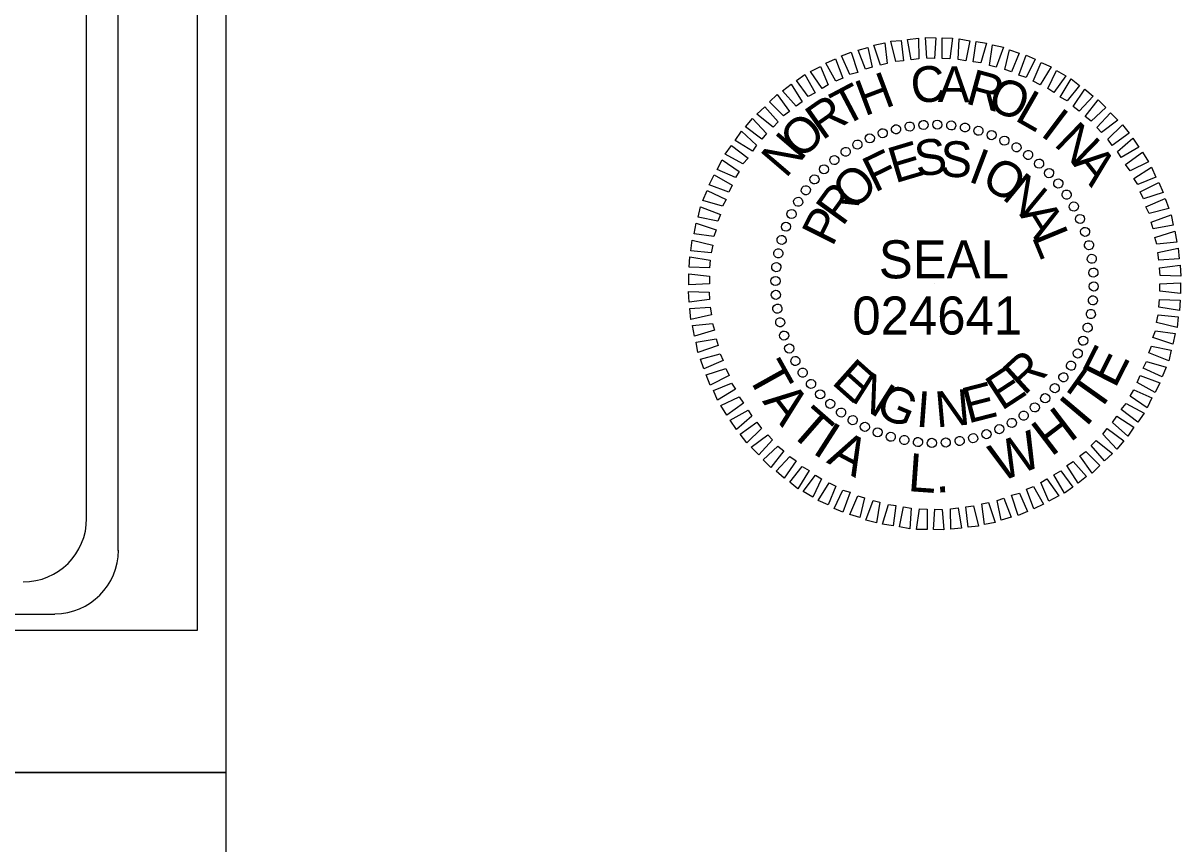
# Model space of a CAD drawing. Extents: x 2241278 to 2254132, y 649924 to 670434.
# Drawn here: x 2252819 to 2253731, y 660843 to 661490 of the extents above; entities that cross this region are included whole.
import ezdxf

# ---------------------------------------------------------------- set-up
doc = ezdxf.new("R2010")
doc.units = 0
for name, color, linetype in [('Sheet Cutting Line CELL', 7, 'Continuous'), ('Sheet Plot Border Inside CELL', 7, 'Continuous'), ('Sheet Plot Border Outside CELL', 7, 'Continuous'), ('Sheet Professional Seal CELL', 7, 'Continuous'), ('Sheet Title CELL', 7, 'Continuous')]:
    doc.layers.add(name, color=color, linetype=linetype)

msp = doc.modelspace()

# ---------------------------------------------------------------- linework, layer by layer
at = {"layer": 'Sheet Cutting Line CELL'}
for p, q in [((2244558.77, 660899.17), (2252978.77, 660899.17)), ((2252978.77, 660899.17), (2244558.77, 660899.17))]:
    msp.add_line(p, q, dxfattribs=at)
at = {"layer": 'Sheet Plot Border Inside CELL'}
msp.add_lwpolyline([(2244623.77, 661011.36), (2252956.27, 661011.36), (2252956.27, 666286.86), (2244623.77, 666286.86)], close=True, dxfattribs=at)
at = {"layer": 'Sheet Plot Border Outside CELL'}
for points in [[(2252978.77, 666399.11), (2244558.77, 666399.11), (2244558.77, 660899.17), (2252978.77, 660899.17)], [(2244558.77, 655399.17), (2252978.77, 655399.17), (2252978.77, 660899.17), (2244558.77, 660899.17)]]:
    msp.add_lwpolyline(points, close=True, dxfattribs=at)
at = {"layer": 'Sheet Professional Seal CELL'}
for p, q in [((2253517.4, 661408.09), (2253517.4, 661408.09)), ((2253528.15, 661409.6), (2253528.15, 661409.6)), ((2253539.15, 661409.85), (2253539.15, 661409.85)), ((2253550.15, 661409.1), (2253550.15, 661409.1)), ((2253485.9, 661399.08), (2253485.9, 661399.08)), ((2253495.9, 661403.09), (2253495.9, 661403.09)), ((2253506.4, 661406.09), (2253506.4, 661406.09)), ((2253560.9, 661407.35), (2253560.9, 661407.35)), ((2253571.4, 661405.11), (2253571.4, 661405.11)), ((2253581.9, 661401.61), (2253581.9, 661401.61)), ((2253476.15, 661394.08), (2253476.15, 661394.08)), ((2253591.9, 661397.11), (2253591.9, 661397.11)), ((2253601.65, 661392.11), (2253601.65, 661392.11)), ((2253457.91, 661382.08), (2253457.91, 661382.08)), ((2253466.65, 661388.33), (2253466.65, 661388.33)), ((2253610.66, 661385.87), (2253610.66, 661385.87)), ((2253449.66, 661374.58), (2253449.66, 661374.58)), ((2253619.41, 661379.12), (2253619.41, 661379.12)), ((2253627.16, 661371.62), (2253627.16, 661371.62)), ((2253442.16, 661366.82), (2253442.16, 661366.82)), ((2253634.66, 661363.37), (2253634.66, 661363.37)), ((2253435.41, 661358.07), (2253435.41, 661358.07)), ((2253640.91, 661354.62), (2253640.91, 661354.62)), ((2253429.16, 661349.07), (2253429.16, 661349.07)), ((2253646.67, 661345.12), (2253646.67, 661345.12)), ((2253424.17, 661339.32), (2253424.17, 661339.32)), ((2253651.67, 661335.38), (2253651.67, 661335.38)), ((2253419.67, 661329.32), (2253419.67, 661329.32)), ((2253416.17, 661318.82), (2253416.17, 661318.82)), ((2253655.67, 661325.38), (2253655.67, 661325.38)), ((2253413.92, 661308.32), (2253413.92, 661308.32)), ((2253658.67, 661314.88), (2253658.67, 661314.88)), ((2253660.68, 661303.88), (2253660.68, 661303.88)), ((2253412.18, 661297.57), (2253412.18, 661297.57)), ((2253662.18, 661293.13), (2253662.18, 661293.13)), ((2253411.43, 661286.57), (2253411.43, 661286.57)), ((2253536.93, 661284.35), (2253536.93, 661284.35)), ((2253662.43, 661282.13), (2253662.43, 661282.13)), ((2253411.68, 661275.57), (2253411.68, 661275.57)), ((2253661.68, 661271.13), (2253661.68, 661271.13)), ((2253413.19, 661264.82), (2253413.19, 661264.82)), ((2253415.19, 661253.82), (2253415.19, 661253.82)), ((2253659.94, 661260.38), (2253659.94, 661260.38)), ((2253657.69, 661249.88), (2253657.69, 661249.88)), ((2253418.19, 661243.32), (2253418.19, 661243.32)), ((2253654.19, 661239.38), (2253654.19, 661239.38)), ((2253422.19, 661233.32), (2253422.19, 661233.32)), ((2253649.69, 661229.38), (2253649.69, 661229.38)), ((2253427.2, 661223.57), (2253427.2, 661223.57)), ((2253644.7, 661219.62), (2253644.7, 661219.62)), ((2253432.95, 661214.07), (2253432.95, 661214.07)), ((2253638.45, 661210.62), (2253638.45, 661210.62)), ((2253439.2, 661205.32), (2253439.2, 661205.32)), ((2253631.7, 661201.87), (2253631.7, 661201.87)), ((2253446.7, 661197.07), (2253446.7, 661197.07)), ((2253454.45, 661189.58), (2253454.45, 661189.58)), ((2253624.2, 661194.12), (2253624.2, 661194.12)), ((2253463.21, 661182.83), (2253463.21, 661182.83)), ((2253607.21, 661180.36), (2253607.21, 661180.36)), ((2253615.96, 661186.62), (2253615.96, 661186.62)), ((2253472.21, 661176.58), (2253472.21, 661176.58)), ((2253481.96, 661171.58), (2253481.96, 661171.58)), ((2253597.71, 661174.61), (2253597.71, 661174.61)), ((2253491.96, 661167.09), (2253491.96, 661167.09)), ((2253502.46, 661163.59), (2253502.46, 661163.59)), ((2253512.96, 661161.34), (2253512.96, 661161.34)), ((2253567.46, 661162.6), (2253567.46, 661162.6)), ((2253577.96, 661165.61), (2253577.96, 661165.61)), ((2253587.96, 661169.61), (2253587.96, 661169.61)), ((2253523.71, 661159.59), (2253523.71, 661159.59)), ((2253534.71, 661158.85), (2253534.71, 661158.85)), ((2253545.71, 661159.1), (2253545.71, 661159.1)), ((2253556.46, 661160.6), (2253556.46, 661160.6))]:
    msp.add_line(p, q, dxfattribs=at)
for points in [[(2253494.39, 661456.59), (2253489.13, 661472.34), (2253497.63, 661474.09), (2253499.64, 661457.84)], [(2253506.39, 661459.34), (2253502.38, 661475.34), (2253510.63, 661476.09), (2253512.39, 661460.09)], [(2253518.39, 661460.84), (2253515.63, 661476.84), (2253524.13, 661477.84), (2253524.39, 661461.59)], [(2253530.89, 661462.1), (2253529.63, 661478.35), (2253537.88, 661478.1), (2253536.89, 661461.85)], [(2253542.89, 661461.85), (2253542.88, 661478.1), (2253551.13, 661477.85), (2253548.89, 661461.6)], [(2253555.39, 661461.1), (2253556.38, 661477.35), (2253564.63, 661475.85), (2253561.39, 661460.1)], [(2253567.39, 661459.1), (2253569.63, 661475.11), (2253577.88, 661473.86), (2253573.39, 661458.36)], [(2253580.14, 661456.36), (2253582.63, 661472.61), (2253591.13, 661470.61), (2253585.39, 661455.11)], [(2253470.14, 661449.33), (2253463.64, 661463.83), (2253471.14, 661466.83), (2253476.39, 661450.83)], [(2253482.39, 661453.33), (2253476.63, 661468.33), (2253484.38, 661470.58), (2253487.64, 661455.08)], [(2253592.14, 661453.11), (2253595.88, 661468.61), (2253603.64, 661466.11), (2253597.39, 661451.36)], [(2253603.39, 661448.61), (2253609.14, 661464.37), (2253616.14, 661461.37), (2253609.14, 661446.87)], [(2253448.39, 661438.08), (2253439.14, 661451.57), (2253446.89, 661455.57), (2253453.14, 661441.08)], [(2253459.14, 661444.08), (2253451.14, 661458.08), (2253458.89, 661461.58), (2253464.64, 661446.33)], [(2253614.64, 661443.87), (2253620.89, 661458.62), (2253628.64, 661455.12), (2253620.14, 661441.12)], [(2253437.39, 661431.82), (2253428.14, 661444.57), (2253434.64, 661449.32), (2253442.89, 661434.82)], [(2253626.14, 661438.12), (2253632.89, 661452.37), (2253640.39, 661448.12), (2253630.89, 661435.12)], [(2253635.89, 661431.37), (2253644.64, 661445.87), (2253651.14, 661440.63), (2253641.39, 661428.37)], [(2253427.9, 661424.32), (2253417.14, 661436.32), (2253423.89, 661441.57), (2253432.64, 661427.57)], [(2253646.15, 661423.87), (2253655.39, 661437.63), (2253661.89, 661432.13), (2253650.9, 661420.38)], [(2253417.9, 661416.57), (2253406.89, 661427.56), (2253412.89, 661433.57), (2253422.65, 661420.07)], [(2253655.65, 661416.13), (2253665.89, 661429.13), (2253671.9, 661423.13), (2253660.4, 661412.38)], [(2253409.65, 661407.82), (2253396.9, 661418.06), (2253403.15, 661423.81), (2253413.65, 661411.82)], [(2253664.65, 661407.38), (2253675.4, 661419.13), (2253681.4, 661413.13), (2253668.4, 661403.38)], [(2253400.9, 661398.31), (2253387.9, 661408.06), (2253393.4, 661414.56), (2253404.4, 661402.81)], [(2253673.4, 661398.38), (2253684.9, 661409.63), (2253690.15, 661402.89), (2253676.9, 661393.38)], [(2253393.4, 661388.81), (2253379.9, 661397.31), (2253384.65, 661404.56), (2253396.65, 661393.56)], [(2253680.9, 661388.63), (2253693.15, 661399.14), (2253697.9, 661391.89), (2253683.91, 661383.88)], [(2253385.91, 661378.81), (2253371.91, 661386.31), (2253376.9, 661393.31), (2253389.91, 661383.31)], [(2253379.91, 661368.06), (2253365.66, 661374.3), (2253369.41, 661382.06), (2253382.91, 661372.81)], [(2253687.41, 661378.38), (2253700.65, 661387.89), (2253705.41, 661380.39), (2253690.91, 661373.39)], [(2253693.91, 661367.39), (2253707.91, 661376.14), (2253711.16, 661368.39), (2253696.91, 661362.64)], [(2253374.91, 661356.56), (2253359.41, 661362.3), (2253363.16, 661370.05), (2253377.41, 661362.06)], [(2253698.91, 661356.64), (2253713.66, 661364.14), (2253716.91, 661356.14), (2253701.41, 661351.14)], [(2253369.92, 661345.56), (2253354.41, 661350.05), (2253357.66, 661357.8), (2253372.66, 661350.81)], [(2253366.17, 661333.55), (2253350.67, 661336.8), (2253352.42, 661345.05), (2253368.17, 661338.81)], [(2253703.42, 661344.89), (2253718.66, 661351.39), (2253721.42, 661343.64), (2253705.92, 661339.64)], [(2253707.42, 661332.89), (2253723.42, 661338.64), (2253724.92, 661330.39), (2253709.17, 661327.64)], [(2253362.92, 661321.55), (2253347.42, 661323.55), (2253349.17, 661332.05), (2253364.92, 661326.8)], [(2253710.42, 661320.89), (2253726.17, 661325.64), (2253727.67, 661317.14), (2253711.92, 661315.64)], [(2253360.92, 661308.8), (2253344.92, 661310.3), (2253345.92, 661318.8), (2253362.17, 661314.8)], [(2253712.67, 661308.89), (2253728.92, 661312.4), (2253729.68, 661303.9), (2253713.68, 661302.89)], [(2253359.68, 661296.8), (2253343.43, 661297.3), (2253343.93, 661305.55), (2253360.18, 661302.8)], [(2253714.18, 661296.89), (2253730.43, 661298.9), (2253730.93, 661290.4), (2253714.68, 661290.89)], [(2253359.43, 661284.3), (2253343.18, 661283.55), (2253343.18, 661292.05), (2253359.43, 661290.3)], [(2253714.43, 661284.39), (2253730.68, 661285.15), (2253730.68, 661276.65), (2253714.43, 661278.39)], [(2253359.68, 661271.8), (2253343.43, 661269.8), (2253342.93, 661278.3), (2253359.18, 661277.8)], [(2253714.18, 661271.89), (2253730.43, 661271.4), (2253729.94, 661263.15), (2253713.69, 661265.89)], [(2253361.19, 661259.8), (2253344.94, 661256.3), (2253344.19, 661264.8), (2253360.19, 661265.8)], [(2253363.44, 661247.8), (2253347.69, 661243.05), (2253346.19, 661251.55), (2253361.94, 661253.05)], [(2253712.94, 661259.89), (2253728.94, 661258.4), (2253727.94, 661249.89), (2253711.69, 661253.89)], [(2253710.94, 661247.14), (2253726.44, 661245.14), (2253724.69, 661236.64), (2253708.94, 661241.89)], [(2253366.44, 661235.8), (2253350.44, 661230.05), (2253348.94, 661238.3), (2253364.69, 661241.05)], [(2253707.69, 661235.14), (2253723.19, 661231.89), (2253721.45, 661223.64), (2253705.69, 661229.89)], [(2253370.45, 661223.81), (2253355.2, 661217.3), (2253352.45, 661225.05), (2253367.94, 661229.05)], [(2253374.95, 661212.06), (2253360.2, 661204.55), (2253356.95, 661212.55), (2253372.45, 661217.56)], [(2253703.95, 661223.14), (2253719.45, 661218.64), (2253716.2, 661210.89), (2253701.2, 661217.89)], [(2253698.95, 661212.14), (2253714.45, 661206.39), (2253710.7, 661198.64), (2253696.45, 661206.64)], [(2253379.95, 661201.31), (2253365.95, 661192.55), (2253362.7, 661200.3), (2253376.95, 661206.06)], [(2253693.95, 661200.64), (2253708.2, 661194.39), (2253704.46, 661186.64), (2253690.95, 661195.89)], [(2253386.45, 661190.31), (2253373.21, 661180.81), (2253368.45, 661188.31), (2253382.95, 661195.31)], [(2253687.95, 661189.88), (2253701.96, 661182.39), (2253696.96, 661175.39), (2253683.96, 661185.38)], [(2253392.96, 661180.06), (2253380.71, 661169.56), (2253375.96, 661176.81), (2253389.96, 661184.81)], [(2253680.46, 661179.88), (2253693.96, 661171.39), (2253689.21, 661164.14), (2253677.21, 661175.13)], [(2253400.46, 661170.31), (2253388.96, 661159.06), (2253383.71, 661165.81), (2253396.96, 661175.31)], [(2253409.21, 661161.32), (2253398.46, 661149.56), (2253392.46, 661155.56), (2253405.46, 661165.31)], [(2253672.96, 661170.38), (2253685.96, 661160.63), (2253680.46, 661154.13), (2253669.46, 661165.88)], [(2253418.21, 661152.57), (2253407.97, 661139.56), (2253401.97, 661145.56), (2253413.46, 661156.32)], [(2253664.21, 661160.88), (2253676.96, 661150.63), (2253670.72, 661144.88), (2253660.21, 661156.88)], [(2253427.72, 661144.82), (2253418.47, 661131.07), (2253411.97, 661136.57), (2253422.96, 661148.32)], [(2253645.97, 661144.37), (2253656.72, 661132.38), (2253649.97, 661127.13), (2253641.22, 661141.12)], [(2253655.96, 661152.13), (2253666.97, 661141.13), (2253660.97, 661135.13), (2253651.21, 661148.63)], [(2253437.97, 661137.32), (2253429.22, 661122.82), (2253422.72, 661128.07), (2253432.47, 661140.32)], [(2253636.47, 661136.87), (2253645.72, 661124.12), (2253639.22, 661119.37), (2253630.97, 661133.87)], [(2253447.72, 661130.57), (2253440.97, 661116.32), (2253433.47, 661120.57), (2253442.97, 661133.57)], [(2253459.22, 661124.83), (2253452.97, 661110.08), (2253445.22, 661113.57), (2253453.72, 661127.58)], [(2253625.47, 661130.62), (2253634.72, 661117.12), (2253626.97, 661113.12), (2253620.72, 661127.62)], [(2253470.47, 661120.08), (2253464.73, 661104.33), (2253457.72, 661107.33), (2253464.72, 661121.83)], [(2253481.72, 661115.58), (2253477.98, 661100.08), (2253470.23, 661102.58), (2253476.47, 661117.33)], [(2253603.72, 661119.36), (2253610.23, 661104.87), (2253602.73, 661101.86), (2253597.47, 661117.86)], [(2253614.72, 661124.62), (2253622.72, 661110.62), (2253614.98, 661107.12), (2253609.22, 661122.37)], [(2253493.72, 661112.34), (2253491.23, 661096.09), (2253482.73, 661098.08), (2253488.47, 661113.59)], [(2253506.47, 661109.59), (2253504.23, 661093.59), (2253495.98, 661094.84), (2253500.47, 661110.34)], [(2253518.47, 661107.59), (2253517.48, 661091.34), (2253509.23, 661092.84), (2253512.47, 661108.59)], [(2253530.98, 661106.85), (2253530.98, 661090.6), (2253522.73, 661090.84), (2253524.98, 661107.09)], [(2253542.98, 661106.6), (2253544.23, 661090.35), (2253535.98, 661090.6), (2253536.98, 661106.85)], [(2253555.47, 661107.85), (2253558.23, 661091.85), (2253549.73, 661090.85), (2253549.48, 661107.1)], [(2253567.47, 661109.35), (2253571.48, 661093.36), (2253563.23, 661092.6), (2253561.47, 661108.6)], [(2253579.47, 661112.11), (2253584.73, 661096.36), (2253576.23, 661094.61), (2253574.22, 661110.86)], [(2253591.47, 661115.36), (2253597.23, 661100.36), (2253589.48, 661098.11), (2253586.22, 661113.61)]]:
    msp.add_lwpolyline(points, close=True, dxfattribs=at)
for centre, major_axis in [((2253506.56, 661406.01), (-0.87, 3.49)), ((2253517.28, 661408.2), (-0.56, 3.56)), ((2253528.15, 661409.44), (-0.25, 3.59)), ((2253539.09, 661409.73), (0.06, 3.6)), ((2253550.01, 661409.06), (0.38, 3.58)), ((2253560.83, 661407.45), (0.69, 3.53)), ((2253571.47, 661404.9), (0.99, 3.46)), ((2253485.9, 661398.89), (-1.47, 3.29)), ((2253496.07, 661402.91), (-1.17, 3.4)), ((2253581.84, 661401.43), (1.29, 3.36)), ((2253591.87, 661397.07), (1.58, 3.24)), ((2253466.78, 661388.29), (-2.01, 2.98)), ((2253476.11, 661394.01), (-1.75, 3.15)), ((2253601.49, 661391.85), (1.85, 3.09)), ((2253610.61, 661385.82), (2.12, 2.91)), ((2253457.99, 661381.78), (-2.27, 2.8)), ((2253619.18, 661379.01), (2.36, 2.72)), ((2253449.8, 661374.53), (-2.5, 2.59)), ((2253627.11, 661371.48), (2.59, 2.5)), ((2253435.46, 661358.03), (-2.91, 2.12)), ((2253442.27, 661366.59), (-2.72, 2.36)), ((2253634.37, 661363.29), (2.8, 2.27)), ((2253429.43, 661348.91), (-3.09, 1.85)), ((2253640.87, 661354.5), (2.98, 2.01)), ((2253646.59, 661345.17), (3.15, 1.75)), ((2253424.21, 661339.29), (-3.24, 1.58)), ((2253651.48, 661335.38), (3.29, 1.47)), ((2253419.85, 661329.26), (-3.36, 1.29)), ((2253655.49, 661325.2), (3.4, 1.17)), ((2253416.38, 661318.88), (-3.46, 0.99)), ((2253658.6, 661314.71), (3.49, 0.87)), ((2253413.83, 661308.24), (-3.53, 0.69)), ((2253660.78, 661304), (3.56, 0.56)), ((2253412.21, 661297.42), (-3.58, 0.38)), ((2253411.55, 661286.5), (-3.6, 0.06)), ((2253662.02, 661293.13), (3.59, 0.25)), ((2253662.31, 661282.19), (3.6, -0.06)), ((2253411.84, 661275.57), (-3.59, -0.25)), ((2253661.65, 661271.27), (3.58, -0.38)), ((2253413.08, 661264.7), (-3.56, -0.56)), ((2253660.03, 661260.45), (3.53, -0.69)), ((2253415.26, 661253.98), (-3.49, -0.87)), ((2253657.48, 661249.81), (3.46, -0.99)), ((2253418.37, 661243.49), (-3.4, -1.17)), ((2253654.01, 661239.44), (3.36, -1.29)), ((2253422.38, 661233.31), (-3.29, -1.47)), ((2253427.27, 661223.52), (-3.15, -1.75)), ((2253649.65, 661229.4), (3.24, -1.58)), ((2253432.99, 661214.2), (-2.98, -2.01)), ((2253644.44, 661219.79), (3.09, -1.85)), ((2253439.5, 661205.41), (-2.8, -2.27)), ((2253638.4, 661210.66), (2.91, -2.12)), ((2253446.75, 661197.21), (-2.59, -2.5)), ((2253624.06, 661194.16), (2.5, -2.59)), ((2253631.59, 661202.1), (2.72, -2.36)), ((2253454.68, 661189.69), (-2.36, -2.72)), ((2253615.87, 661186.91), (2.27, -2.8)), ((2253463.25, 661182.88), (-2.12, -2.91)), ((2253472.37, 661176.84), (-1.85, -3.09)), ((2253607.08, 661180.4), (2.01, -2.98)), ((2253481.99, 661171.62), (-1.58, -3.24)), ((2253492.02, 661167.26), (-1.29, -3.36)), ((2253587.96, 661169.8), (1.47, -3.29)), ((2253597.75, 661174.69), (1.75, -3.15)), ((2253502.4, 661163.8), (-0.99, -3.46)), ((2253513.03, 661161.25), (-0.69, -3.53)), ((2253523.85, 661159.63), (-0.38, -3.58)), ((2253534.77, 661158.97), (-0.06, -3.6)), ((2253545.71, 661159.25), (0.25, -3.59)), ((2253556.58, 661160.5), (0.56, -3.56)), ((2253567.3, 661162.68), (0.87, -3.49)), ((2253577.79, 661165.79), (1.17, -3.4))]:
    msp.add_ellipse(centre, major_axis=major_axis, ratio=0.999708, dxfattribs=at)
at = {"layer": 'Sheet Title CELL'}
for points in [[(2252893.77, 661074.17), (2252893.77, 666224.11)], [(2252868.77, 661099.17), (2252868.77, 661899.17)], [(2245443.77, 661024.11), (2252843.77, 661024.11)]]:
    msp.add_lwpolyline(points, dxfattribs=at)
for centre in [(2252818.79, 661099.4), (2252843.79, 661074.4)]:
    msp.add_arc(centre, 50, 270, 360, dxfattribs=at)

# ---------------------------------------------------------------- texts
at = {"layer": 'Sheet Professional Seal CELL'}
for s, height, rotation, p in [('C', 28.19, 6.23419, (2253519.65, 661426.09)), ('A', 28.19, 359.03464, (2253539.39, 661427.6)), ('H', 28.19, 20.6338, (2253481.65, 661416.08)), ('R', 28.19, 344.63542, (2253560.4, 661426.6)), ('O', 28.19, 337.43548, (2253577.15, 661422.86)), ('T', 28.19, 27.83409, (2253465.4, 661407.83)), ('L', 28.19, 330.23519, (2253599.15, 661413.61)), ('R', 28.19, 35.03482, (2253448.4, 661396.83)), ('I', 28.19, 323.03446, (2253619.4, 661401.62)), ('O', 28.19, 42.23606, (2253431.16, 661381.32)), ('N', 28.19, 315.83323, (2253630.15, 661393.87)), ('N', 28.19, 49.43782, (2253419.66, 661366.82)), ('S', 28.19, 7.26993, (2253522.91, 661368.59)), ('F', 28.19, 25.98135, (2253489.66, 661355.84)), ('E', 28.19, 16.62539, (2253505.66, 661363.34)), ('S', 28.19, 357.91472, (2253540.91, 661368.85)), ('I', 28.19, 339.20392, (2253562.41, 661365.35)), ('O', 28.19, 329.8478, (2253572.41, 661361.86)), ('A', 28.19, 308.63147, (2253644.91, 661379.12)), ('O', 28.19, 44.69556, (2253473.17, 661341.08)), ('N', 28.19, 320.49093, (2253589.16, 661351.86)), ('R', 28.2, 54.05397, (2253464.42, 661328.83)), ('P', 28.2, 63.41321, (2253456.42, 661312.83)), ('A', 28.2, 301.77459, (2253603.42, 661338.86)), ('L', 28.2, 292.41517, (2253613.17, 661321.62)), ('SEAL', 29.991, 0.01432, (2253492.93, 661288.58)), ('024641', 29.991, 0.01432, (2253472.08, 661244.29)), ('E', 29.99, 63.13321, (2253679.11, 661201.11)), ('T', 29.99, 299.17946, (2253388.47, 661212.9)), ('R', 28.19, 42.49573, (2253607.45, 661195.61)), ('E', 28.19, 318.29121, (2253454.95, 661206.08)), ('E', 28.19, 33.13841, (2253589.71, 661183.86)), ('T', 29.99, 54.61139, (2253665.21, 661180.96)), ('N', 28.19, 327.64827, (2253469.95, 661192.58)), ('E', 28.19, 14.42608, (2253563.21, 661174.1)), ('A', 29.99, 307.70128, (2253400.7, 661191.69)), ('G', 28.19, 337.00456, (2253488.96, 661181.34)), ('I', 28.19, 355.71552, (2253521.71, 661171.84)), ('N', 28.19, 5.07071, (2253538.46, 661171.1)), ('T', 29.99, 318.77965, (2253421.04, 661167.24)), ('I', 29.99, 49.84692, (2253656.18, 661170.66)), ('H', 29.99, 37.33533, (2253628.72, 661147.53)), ('I', 29.99, 327.30147, (2253439.68, 661151.36)), ('A', 29.99, 332.06594, (2253451.06, 661143.74)), ('W', 29.99, 21.62807, (2253588.25, 661127.79)), ('L', 29.99, 355.92704, (2253515.28, 661121.02)), ('.', 29.99, 3.79035, (2253537.82, 661119.59))]:
    msp.add_text(s, height=height, rotation=rotation, dxfattribs=at).set_placement(p)

doc.saveas('drawing.dxf')
